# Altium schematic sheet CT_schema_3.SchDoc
size 298 x 247 mm
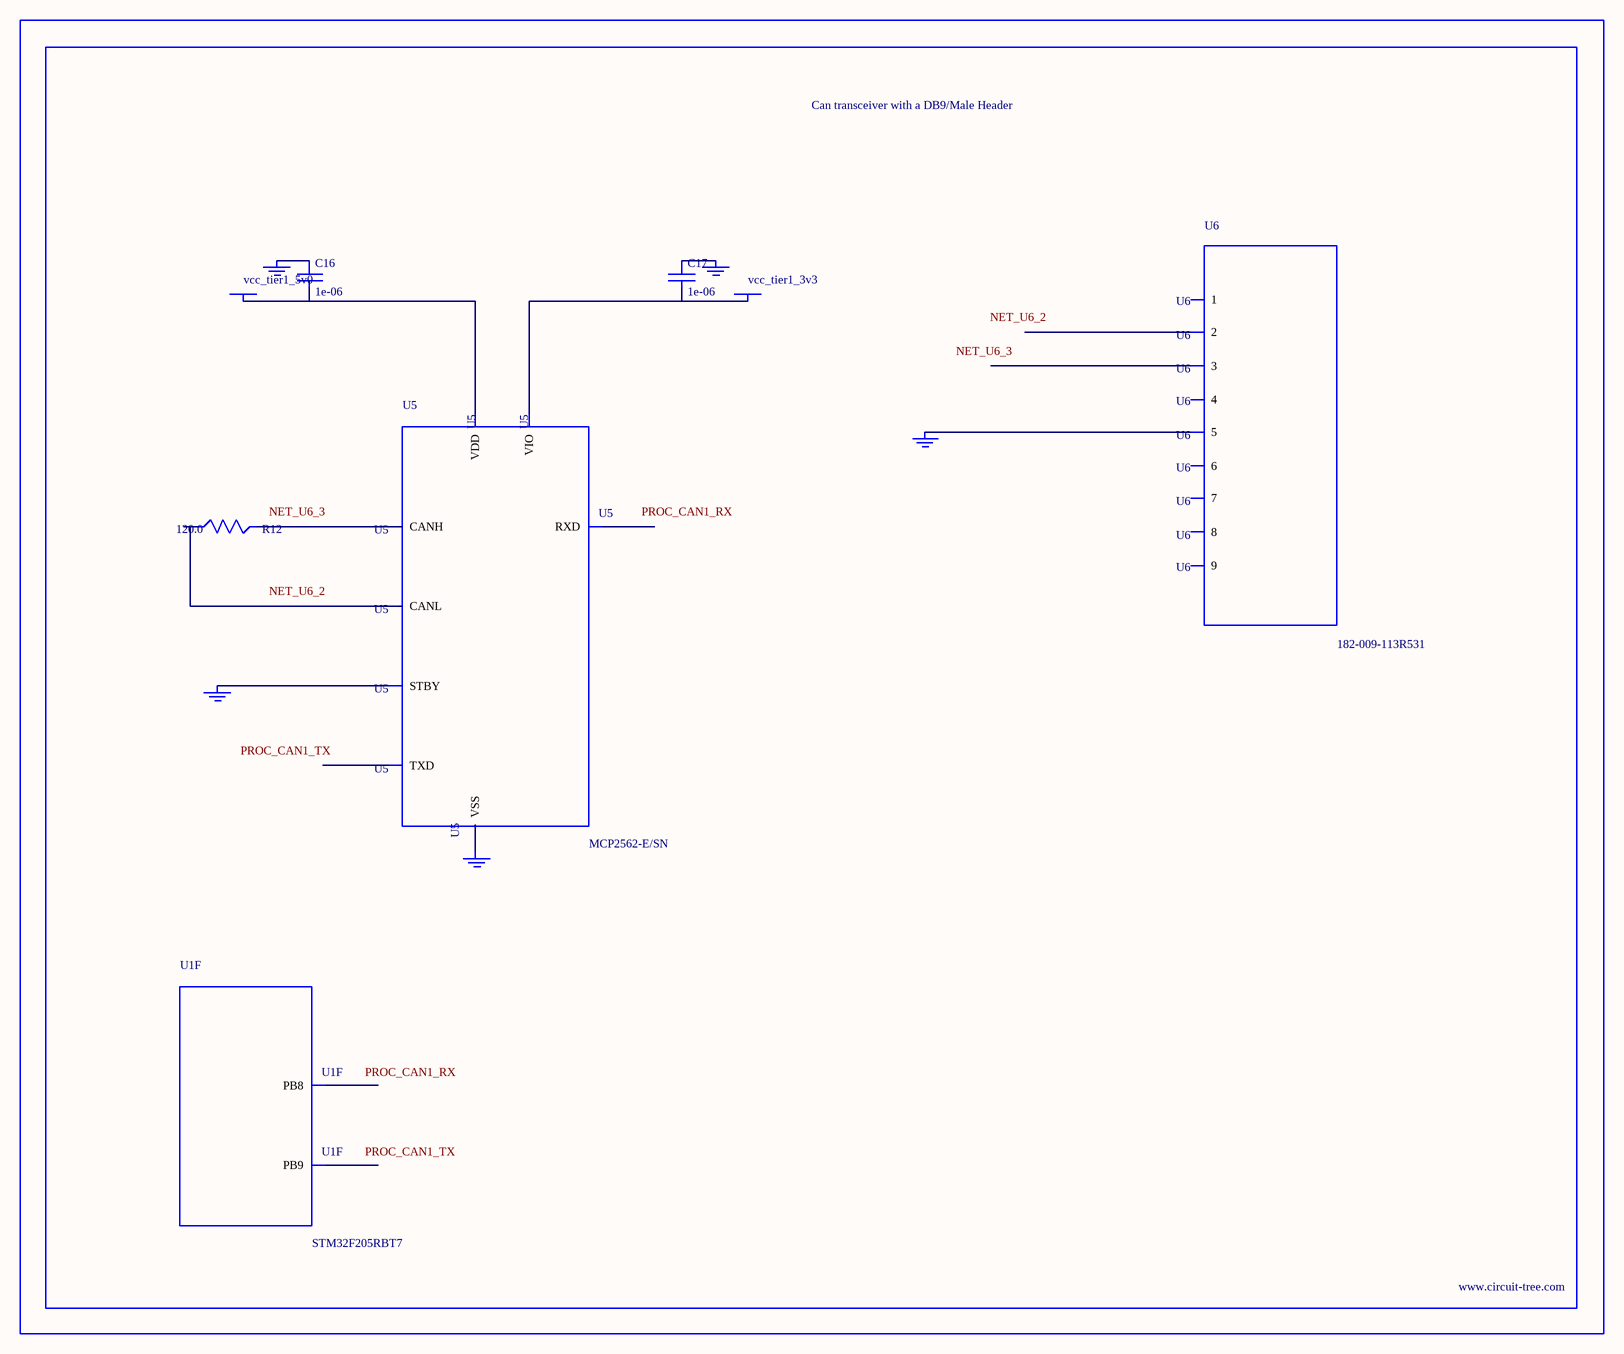
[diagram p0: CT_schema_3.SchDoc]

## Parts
BORDER2  (no value)
C16  1e-06  [C0603]
C17  1e-06  [C0603]
GND_INSTANCE_2_0  (no value)
GND_INSTANCE_2_1  (no value)
GND_INSTANCE_2_2  (no value)
GND_INSTANCE_2_3  (no value)
GND_INSTANCE_2_4  (no value)
POWER_INSTANCE_2_0  vcc_tier1_5v0
POWER_INSTANCE_2_1  vcc_tier1_3v3
R12  120.0  [R0603]
U1  STM32F205RBT7  [LQFP64]  (part F of 7)
U5  MCP2562-E/SN  [SOIC-8]
U6  182-009-113R531  [182-009-MALE]

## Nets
NetC16_1: C16.1 GND_INSTANCE_2_0.0(GND)
NetC16_2: C16.2 POWER_INSTANCE_2_0.0(PWR) U5.3(VDD)
NetC17_1: C17.1 GND_INSTANCE_2_1.0(GND)
NetC17_2: C17.2 POWER_INSTANCE_2_1.0(PWR) U5.5(VIO)
NetGND_INSTANCE_2_2_0: GND_INSTANCE_2_2.0(GND) U5.8(STBY)
NetGND_INSTANCE_2_3_0: GND_INSTANCE_2_3.0(GND) U5.2(VSS)
NetGND_INSTANCE_2_4_0: GND_INSTANCE_2_4.0(GND) U6.5
NetR12_1: R12.1 U5.6(CANL)
NetR12_2: R12.2 U5.7(CANH)

Not connected (* = marked no-connect by the designer): U1 61(PB8) 62(PB9); U5 1(TXD) 4(RXD); U6 1 2 3 4 6 7 8 9

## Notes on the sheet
- Labels drawn without touching a wire or pin: NET_U6_2, NET_U6_3, PROC_CAN1_RX, PROC_CAN1_TX

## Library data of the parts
BORDER2 = BORDER_PAGE2
C16 C17 = C0603C105K3RACTU
GND_INSTANCE_2_0-GND_INSTANCE_2_4 = GND
POWER_INSTANCE_2_0 POWER_INSTANCE_2_1 = PWR
R12 = RC0603JR-07120RL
